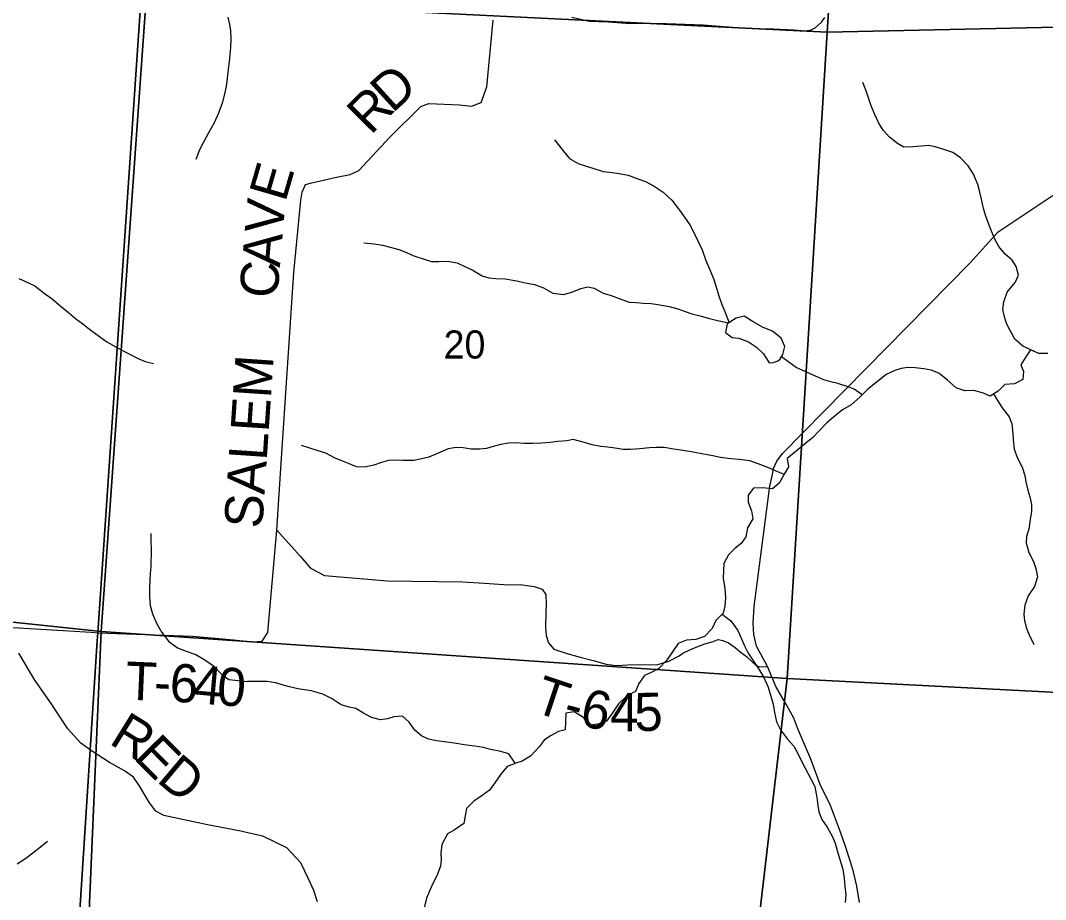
# Model space of a CAD drawing. Extents: x 1578669 to 1989827, y 208020 to 553079.
# Drawn here: x 1860103 to 1868162, y 355126 to 362037 of the extents above; entities that cross this region are included whole.
import ezdxf

# ---------------------------------------------------------------- set-up
doc = ezdxf.new("R2010")
doc.units = 0
for name, color, linetype in [('GM_X_County_Road', 7, 'Continuous'), ('GM_X_County_Road_Text', 7, 'Continuous'), ('GM_X_Minor_Lake', 7, 'Continuous'), ('GM_X_Minor_River', 7, 'Continuous'), ('GM_X_Section', 7, 'Continuous'), ('GM_X_Section_Text', 7, 'Continuous'), ('GM_X_State_Route', 7, 'Continuous'), ('GM_X_Township', 7, 'Continuous'), ('GM_X_Township_Road', 7, 'Continuous'), ('GM_X_Township_Road_Text', 7, 'Continuous')]:
    doc.layers.add(name, color=color, linetype=linetype)

msp = doc.modelspace()

# ---------------------------------------------------------------- linework, layer by layer
at = {"layer": 'GM_X_County_Road'}
for points in [[(1860670, 356290.4), (1860650.8, 356302.9), (1860578.7, 356356.7), (1860476.4, 356467.9), (1860338.5, 356674.7), (1860216.3, 356850.3), (1860089.2, 357063.4)], [(1861902.3, 355649.3), (1861835.4, 355664.6), (1861572.8, 355714.5), (1861230.9, 355786.4), (1861166.3, 355820.1), (1861116.8, 355887.6), (1861036.7, 356023.2), (1860992.2, 356087.7), (1860921.1, 356138.8), (1860803.3, 356203.3), (1860670, 356290.4)], [(1862438.6, 355108.2), (1862410.6, 355196.7), (1862364.6, 355295.2), (1862308.5, 355415.9), (1862198.1, 355532.7), (1862008.5, 355625), (1861902.3, 355649.3)]]:
    msp.add_lwpolyline(points, dxfattribs=at)
at = {"layer": 'GM_X_Minor_Lake'}
for points in [[(1866097.8, 359412.4), (1866112.2, 359474.4), (1866084.6, 359540.7), (1866015, 359595.1), (1865943.2, 359623.6), (1865863.5, 359668.1), (1865791.9, 359712.6), (1865729.8, 359697), (1865659.5, 359651.3), (1865645.1, 359585.3), (1865698.9, 359545), (1865750.8, 359538.7), (1865826.6, 359512.2), (1865890.3, 359469.8), (1865943.9, 359415.4), (1865989.5, 359345)], [(1865989.5, 359345), (1866021.7, 359347.6), (1866053.1, 359359.4), (1866073.8, 359373.1), (1866097.8, 359412.4)]]:
    msp.add_lwpolyline(points, dxfattribs=at)
at = {"layer": 'GM_X_Minor_River'}
for points in [[(1861732.7, 362063.6), (1861747.6, 362005.2), (1861754.6, 361955), (1861757.4, 361892.8), (1861754.1, 361822.7), (1861749.1, 361770.7), (1861744, 361712.7), (1861736.8, 361654.7), (1861727.4, 361582.8), (1861720.2, 361518.8), (1861707.1, 361460.9), (1861691.8, 361395.1), (1861660.1, 361309.5), (1861626.6, 361234), (1861578.9, 361148.8), (1861541.6, 361081.4), (1861510.4, 361019.9), (1861480.9, 360944.3)], [(1868110.9, 359418.4), (1867985.3, 359477.2), (1867921.7, 359531.7), (1867886.1, 359594), (1867854.5, 359654.2), (1867838.8, 359708.4), (1867827.2, 359764.5), (1867833.6, 359824.5), (1867862, 359900.5), (1867924.5, 359976.2), (1867950.8, 360034.1), (1867931.2, 360102.3), (1867899.6, 360152.5), (1867843.9, 360200.9), (1867796.3, 360261.3), (1867762.7, 360317.5), (1867731.2, 360393.8), (1867711.5, 360448), (1867693.8, 360498.2), (1867674.2, 360560.4), (1867658.7, 360632.5), (1867645, 360688.7), (1867629.4, 360746.8), (1867595.9, 360829.1), (1867554.3, 360893.5), (1867492.8, 360957.9), (1867433.1, 360998.3), (1867355.3, 361026.8), (1867295.4, 361045.2), (1867243.5, 361053.5), (1867183.5, 361049.9), (1867121.5, 361044.2), (1867049.5, 361042.7), (1866997.7, 361071), (1866936.1, 361121.4), (1866886.4, 361175.8), (1866852.8, 361230.1), (1866817.3, 361302.3), (1866791.7, 361366.6), (1866772, 361420.8), (1866754.4, 361476.9), (1866726.8, 361549.2)], [(1864301.2, 361099.1), (1864370.6, 361012.6), (1864420.2, 360952.3), (1864488, 360913.8), (1864549.8, 360893.4), (1864603.7, 360875.1), (1864683.5, 360850.6), (1864755.4, 360842.1), (1864809.3, 360833.8), (1864881.2, 360821.4), (1864965, 360788.8), (1865016.8, 360770.5), (1865084.6, 360736), (1865156.2, 360687.6), (1865223.8, 360625.1), (1865283.3, 360546.6), (1865322.9, 360492.3), (1865364.5, 360430), (1865398.1, 360371.8), (1865429.7, 360305.5), (1865463.3, 360233.2), (1865492.7, 360150.9), (1865526.2, 360072.6), (1865555.8, 360000.4), (1865579.3, 359924.1), (1865594.9, 359872), (1865618.5, 359805.8), (1865640.2, 359749.6), (1865674, 359660.8)], [(1862802.9, 360289.2), (1862884.8, 360280.7), (1862948.7, 360270.3), (1863020.6, 360251.8), (1863078.4, 360237.5), (1863138.3, 360213.1), (1863196.1, 360186.7), (1863275.9, 360160.2), (1863333.7, 360143.8), (1863391.7, 360143.5), (1863459.7, 360145.1), (1863535.6, 360132.6), (1863601.3, 360100.2), (1863653.2, 360075.8), (1863732.8, 360029.3), (1863786.7, 360013), (1863840.6, 360008.6), (1863914.6, 360006.2), (1864004.4, 359989.6), (1864070.3, 359975.2), (1864144.2, 359960.8), (1864216, 359934.3), (1864289.7, 359893.8), (1864373.6, 359883.3), (1864437.7, 359900.9), (1864507.8, 359930.5), (1864561.9, 359944.2), (1864613.8, 359931.9), (1864683.5, 359893.5), (1864747.4, 359875.1), (1864811.2, 359852.6), (1864889, 359824.1), (1864944.9, 359819.8), (1864998.9, 359815.5), (1865060.8, 359811.1), (1865114.8, 359804.8), (1865204.6, 359788.2), (1865272.5, 359769.8), (1865328.3, 359749.4), (1865382.2, 359731.1), (1865448, 359714.7), (1865509.9, 359698.3), (1865583.7, 359679.8), (1865672.1, 359659.5)], [(1860089.5, 360009.8), (1860141.1, 359984.7), (1860216.5, 359951.2), (1860289.5, 359893.6), (1860352.7, 359850.3), (1860425.6, 359786.7), (1860480.7, 359741.5), (1860535.9, 359694.3), (1860593.2, 359653.1), (1860644.4, 359610), (1860695.7, 359574.9), (1860780.6, 359511.1), (1860853.9, 359471.6), (1860925.2, 359432.1), (1860976.8, 359407.1), (1861032.3, 359377.9), (1861083.9, 359356.8), (1861149.6, 359339.5)], [(1868110.9, 359418.4), (1868045.1, 359448.8), (1868008.8, 359393), (1867968.4, 359331.2), (1867988.1, 359279), (1867983.7, 359214.9), (1867919.5, 359181.3), (1867843.5, 359175.7), (1867791.2, 359124), (1867727, 359084.3), (1867675.2, 359106.6), (1867599.3, 359127.1), (1867527.4, 359125.6), (1867459.5, 359150), (1867391.9, 359208.5), (1867324.3, 359264.9), (1867264.5, 359289.3), (1867204.6, 359299.7), (1867136.7, 359306.1), (1867080.7, 359308.4), (1867026.7, 359300.8), (1866976.6, 359285), (1866910.4, 359253.4), (1866828.1, 359189.8), (1866765.8, 359140.1), (1866703.4, 359076.4), (1866633.1, 359016.8), (1866564.9, 358977.1), (1866496.5, 358917.5), (1866442.3, 358873.8), (1866384, 358812), (1866331.6, 358758.3), (1866277.4, 358714.5), (1866203, 358650.9), (1866130.7, 358593.3), (1866142.3, 358527.1), (1866108, 358471.3), (1866069.5, 358399.4), (1866015.3, 358355.7), (1865937.4, 358364.2), (1865867.4, 358360.6), (1865825.1, 358304.8), (1865824.7, 358250.7), (1865850.3, 358182.5), (1865859.9, 358118.3), (1865819.5, 358048.5), (1865807, 357978.5), (1865770.7, 357926.7), (1865718.5, 357886.9), (1865670.2, 357835.2), (1865633.8, 357769.3), (1865629.5, 357713.2), (1865627.1, 357653.2), (1865640.6, 357571), (1865646.1, 357500.9), (1865641.7, 357432.8), (1865627.4, 357376.9), (1865569.1, 357319.1), (1865540.7, 357257.2), (1865480.3, 357195.5), (1865414.2, 357171.9), (1865340.2, 357164.3), (1865274.1, 357138.7), (1865229.7, 357072.9), (1865181.3, 357005.1), (1865122.9, 356941.4), (1865062.8, 356911.7), (1865008.6, 356888), (1864964.3, 356824.2), (1864937.9, 356762.3), (1864871.7, 356726.6), (1864805.3, 356665), (1864758.9, 356593.1), (1864710.5, 356529.4), (1864642.4, 356505.7), (1864582.4, 356498.1), (1864528.8, 356558.5), (1864455.1, 356601), (1864391.1, 356591.3), (1864388.7, 356523.3), (1864384.3, 356461.2), (1864334.2, 356447.5), (1864270, 356413.9), (1864219.8, 356378.1), (1864181.5, 356326.3), (1864113.1, 356252.6), (1864046.9, 356213), (1863996.8, 356199.2), (1863928.7, 356171.6), (1863880.3, 356111.8), (1863831.9, 356044), (1863791.6, 355986.2), (1863733.4, 355944.5), (1863667.1, 355898.9), (1863610.8, 355841.1), (1863598.4, 355783.1), (1863588.1, 355723.1), (1863513.8, 355671.5), (1863459.6, 355643.8), (1863415.1, 355560), (1863408.7, 355491.9)], [(1866720.9, 359094.2), (1866657.9, 359138.8), (1866604, 359161.1), (1866530.2, 359183.6), (1866474.3, 359195.9), (1866418.4, 359212.3), (1866352.6, 359240.7), (1866278.9, 359275.2), (1866203.1, 359309.7), (1866086.7, 359394.2)], [(1868180.9, 359420), (1868110.9, 359418.4)], [(1867754.4, 359101.2), (1867784.8, 359049.9), (1867822.4, 358991.6), (1867877.9, 358921.2), (1867897.5, 358865), (1867905.1, 358790.9), (1867908.8, 358740.8), (1867916.3, 358666.7), (1867941.9, 358596.5), (1867979.4, 358526.2), (1868001, 358460), (1868006.7, 358409.9), (1868024.2, 358343.7), (1868037.9, 358291.5), (1868051.5, 358231.4), (1868053.2, 358177.3), (1868042.8, 358117.3), (1868030.3, 358039.3), (1868014, 357981.3), (1868009.7, 357931.3), (1868031.2, 357855.1), (1868068.7, 357782.8), (1868086.4, 357728.6), (1868100, 357662.4), (1868075.5, 357588.5), (1868027.1, 357514.7), (1868000.6, 357440.8), (1867992.2, 357370.7), (1867997.9, 357320.6), (1868009.5, 357264.5), (1868033.1, 357206.3), (1868070.7, 357132)], [(1866106.7, 358468.9), (1866040.1, 358495.7), (1865980.3, 358522.1), (1865902.6, 358550.6), (1865836.7, 358575), (1865754.9, 358585.5), (1865686.9, 358591.9), (1865607, 358602.4), (1865547.1, 358614.8), (1865473.2, 358627.3), (1865391.4, 358643.8), (1865329.5, 358654.1), (1865277.6, 358662.5), (1865221.6, 358670.8), (1865167.7, 358681.1), (1865099.8, 358681.5), (1865047.8, 358677.9), (1864973.8, 358670.3), (1864899.8, 358664.7), (1864841.8, 358665.1), (1864779.9, 358675.5), (1864720, 358683.8), (1864666, 358688.1), (1864598.1, 358700.6), (1864528.3, 358721), (1864448.5, 358743.5), (1864398.4, 358733.8), (1864328.4, 358726.2), (1864266.4, 358718.6), (1864198.4, 358713), (1864128.4, 358711.4), (1864062.5, 358711.8), (1863992.5, 358716.2), (1863940.5, 358714.5), (1863878.5, 358702.9), (1863818.4, 358687.2), (1863768.3, 358671.5), (1863714.4, 358667.8), (1863646.4, 358668.2), (1863584.5, 358678.6), (1863528.5, 358680.9), (1863466.5, 358669.3), (1863382.3, 358631.8), (1863314.1, 358604.1), (1863246.1, 358588.5), (1863196, 358576.8), (1863110.1, 358577.3), (1863050.1, 358581.7), (1862996.1, 358578), (1862942.1, 358562.3), (1862882, 358542.6), (1862807.9, 358525.1), (1862746, 358529.4), (1862682.1, 358553.8), (1862630.3, 358574.2), (1862572.5, 358598.5), (1862502.7, 358635), (1862442.9, 358653.4), (1862379, 358673.8), (1862311.2, 358696.2)], [(1861127.9, 358005.2), (1861128.9, 357951.1), (1861129.4, 357872.9), (1861126.8, 357740.7), (1861123.8, 357690.6), (1861120.8, 357636.6), (1861117.6, 357574.5), (1861116.3, 357506.4), (1861123, 357438.1), (1861139.7, 357371.7), (1861176.3, 357294.8), (1861215, 357225.9), (1861267.7, 357158.7), (1861338.8, 357105.2), (1861406.4, 357079.8), (1861481.9, 357052.3), (1861553.2, 357010.8), (1861620.3, 356963.4), (1861685.1, 356895.9), (1861742.4, 356856.7), (1861814.3, 356847.3), (1861888.2, 356839.8)], [(1865621.3, 357370.8), (1865689, 357318.4), (1865742.5, 357242), (1865772.1, 357175.8), (1865795.7, 357119.6), (1865825.3, 357063.3), (1865861, 357009), (1865908.5, 356938.7), (1865948.1, 356872.4), (1865981.6, 356796.1), (1865999.2, 356733.9), (1866020.7, 356661.7), (1866030.3, 356597.6), (1866047.9, 356523.4), (1866079.5, 356461.1), (1866135, 356386.7), (1866182.6, 356332.3), (1866214.2, 356274.1), (1866241.9, 356219.8), (1866271.5, 356159.6), (1866320.9, 356071.2), (1866348.6, 356015), (1866364, 355928.8), (1866371.6, 355866.7), (1866379.3, 355816.6), (1866402.9, 355754.3), (1866446.5, 355694), (1866486, 355623.7), (1866507.7, 355569.5), (1866525.3, 355511.3), (1866544.9, 355441.1), (1866568.4, 355364.9), (1866579.9, 355292.8), (1866585.6, 355232.6), (1866591.1, 355162.5), (1866586.7, 355102.5)], [(1863993, 356197.7), (1863943.3, 356271.6), (1863879.5, 356290), (1863799.6, 356306.5), (1863743.7, 356320.9), (1863675.8, 356331.3), (1863591.9, 356343.8), (1863532, 356352.2), (1863456.1, 356364.7), (1863374.2, 356375.2), (1863310.3, 356387.6), (1863256.5, 356413.9), (1863204.8, 356458.3), (1863159.2, 356520.6), (1863105.6, 356567), (1863039.6, 356561.4), (1862987.5, 356545.7), (1862933.5, 356540), (1862861.6, 356556.4), (1862799.9, 356590.8), (1862740.1, 356627.2), (1862686.2, 356639.6), (1862624.4, 356658), (1862552.7, 356704.5), (1862480.9, 356740.9), (1862387.2, 356767.5), (1862335.2, 356775.8), (1862283.3, 356782.2), (1862219.4, 356798.6), (1862167.5, 356812.9), (1862111.7, 356829.2), (1862043.8, 356841.7), (1861888.2, 356839.8)], [(1860076.8, 355406.5), (1860143.8, 355451.3), (1860210.8, 355500.1), (1860261.6, 355541.2), (1860316.5, 355584.2)], [(1863408.7, 355491.9), (1863410.4, 355441.9), (1863404.1, 355387.8), (1863375.6, 355311.9), (1863347.3, 355258), (1863325, 355206.1), (1863294.6, 355138.2), (1863278.1, 355060.2)]]:
    msp.add_lwpolyline(points, dxfattribs=at)
at = {"layer": 'GM_X_Section'}
for points in [[(1861472.6, 367986), (1866798.8, 367601.9), (1866446.1, 361945.5), (1861091.5, 362209.9)], [(1866798.8, 367601.9), (1872183.4, 367145.3), (1871754, 361853.5), (1869336.4, 362007.7), (1866446.1, 361945.5)], [(1856112.7, 362911.8), (1861091.5, 362209.9), (1860737.7, 357233.4), (1855700.1, 357765.6)], [(1861091.5, 362209.9), (1866446.1, 361945.5), (1866130.8, 356864.4), (1860737.7, 357233.4)], [(1866446.1, 361945.5), (1869336.4, 362007.7), (1871754, 361853.5), (1871398.1, 356592.4), (1866130.8, 356864.4)], [(1855700.1, 357765.6), (1860737.7, 357233.4), (1860524.1, 352292.2), (1855214.2, 352367.7)], [(1860737.7, 357233.4), (1866130.8, 356864.4), (1865572.4, 352090.1), (1860524.1, 352292.2)], [(1866130.8, 356864.4), (1871398.1, 356592.4), (1871076.6, 351475.2), (1867993.2, 351687.8), (1865572.4, 352090.1)]]:
    msp.add_lwpolyline(points, close=True, dxfattribs=at)
at = {"layer": 'GM_X_State_Route'}
msp.add_lwpolyline([(1866700.4, 355104), (1866679.2, 355230.7), (1866651.8, 355343.3), (1866628.3, 355423.7), (1866589, 355542.4), (1866549.5, 355655.2), (1866472.7, 355866.5), (1866391.5, 356031.7), (1866316.5, 356230.9), (1866213.8, 356468.6), (1866184.2, 356551.1), (1866124.7, 356657.9), (1866043.3, 356795), (1865976.1, 356959.7), (1865888.9, 357119.4), (1865869.5, 357209.8), (1865864.1, 357300.2), (1865870.9, 357430.6), (1865995.7, 358377), (1866016.3, 358467.2), (1866022.7, 358515.3), (1866049.2, 358573.3), (1866093.7, 358633.2), (1867566.9, 360129.4), (1867791.4, 360374.6), (1868333.7, 360737.8)], dxfattribs=at)
at = {"layer": 'GM_X_Township'}
for points in [[(1859031.2, 376400.1), (1860929.1, 376280.6), (1862026.2, 376219.4), (1861697.2, 371438.7), (1861646.3, 370710.7), (1861408.8, 367950.9), (1861213, 364441.1), (1861197.1, 363836.4), (1861045.8, 362151.1), (1860710.3, 357224), (1860706, 357161.1), (1860650.8, 356302.9), (1860040.1, 346806.3)], [(1882646.6, 364366.3), (1882063.5, 357591.4), (1881944.6, 356212.8), (1881936, 356109.2), (1881810.5, 354649.5), (1881525.9, 351342.7), (1881414.8, 350049.3), (1881322.2, 347940.9), (1881165.8, 345493.3), (1878346.3, 345681.9), (1874430.1, 345924.2), (1871549.1, 346086.1), (1870033, 346179.3), (1867333.5, 346362.4), (1865771, 346465.4), (1860040.1, 346806.3), (1860650.8, 356302.9), (1860706, 357161.1), (1860710.3, 357224), (1861045.8, 362151.1)]]:
    msp.add_lwpolyline(points, dxfattribs=at)
at = {"layer": 'GM_X_Township_Road'}
for points in [[(1860657.8, 357227.2), (1860710.3, 357224), (1861457, 357197.2), (1861777.1, 357168.3), (1861928.4, 357152.8), (1862003.7, 357158), (1862048, 357226.2), (1862119.6, 358031.3), (1862152.6, 358557.4), (1862253.4, 360057.4), (1862306.5, 360623.6), (1862316.6, 360687.8), (1862344.8, 360748), (1862393.1, 360759.9), (1862588.1, 360805.5), (1862694.6, 360827.3), (1862763, 360857.2), (1863010.5, 361123.6), (1863250, 361361.9), (1863314.4, 361385.8), (1863555.5, 361375.1), (1863647.9, 361362.8), (1863724.3, 361392.6), (1863768.7, 361515), (1863819.8, 362039.1)], [(1864436.7, 362063.4), (1864575.3, 362032.8), (1864726, 362026.4), (1864896.8, 362013.8), (1865111.8, 362017.2), (1865471.5, 362004.1), (1865803, 361977.1), (1866024, 361972.4), (1866184.8, 361963.9), (1866277.2, 361955.6), (1866319.4, 361963.5), (1866351.5, 361979.5), (1866399.8, 362025.5), (1866426, 362061.6)], [(1862119.6, 358031.3), (1862304.1, 357823.9), (1862382.4, 357731.3), (1862492.8, 357674.7), (1862989.1, 357631.1), (1863579.9, 357623.4), (1863752.6, 357614.8), (1863939.5, 357600.2), (1864031.9, 357601.9), (1864142.4, 357587.6), (1864204.7, 357567.3), (1864232.8, 357525), (1864236.7, 357446.7), (1864232.6, 357384.5), (1864230.4, 357268), (1864236.3, 357201.7), (1864254.3, 357143.4), (1864296.4, 357095.1), (1864390.8, 357062.7), (1864503.3, 357032.2), (1864605.7, 357005.8), (1864708.1, 356977.4), (1864786.5, 356967.1), (1864878.9, 356970.9), (1864959.4, 356974.6), (1865051.8, 356972.4), (1865114.1, 356974.2), (1865200.5, 357000.1), (1865280.9, 357042), (1865311.1, 357062), (1865359.4, 357088), (1865415.7, 357109.9), (1865484.1, 357135.8), (1865548.4, 357155.7), (1865588.6, 357169.7), (1865624.7, 357161.5), (1865668.9, 357145.3), (1865721.1, 357109), (1865759.3, 357076.7), (1865811.4, 357036.5), (1865849.5, 357000.2), (1865887.7, 356965.9), (1865915.8, 356955.8), (1865976.1, 356959.7)], [(1859997.7, 357267.5), (1860657.8, 357227.2)]]:
    msp.add_lwpolyline(points, dxfattribs=at)

# ---------------------------------------------------------------- texts
at = {"layer": 'GM_X_County_Road_Text'}
for s, rotation, p in [('R', 328.27513, (1860790.8, 356356.7)), ('E', 314.50606, (1860985.5, 356239)), ('D', 319.8874, (1861165, 356058.4))]:
    msp.add_text(s, height=300, rotation=rotation, dxfattribs=at).set_placement(p)
at = {"layer": 'GM_X_Section_Text'}
msp.add_text('20', height=221, rotation=0.00001, dxfattribs=at).set_placement((1863429.8, 359379.6))
at = {"layer": 'GM_X_Township_Road_Text'}
for s, rotation, p in [('D', 42.30725, (1863026.3, 361302.9)), ('R', 45.34496, (1862856.1, 361130.5)), ('E', 73.74613, (1862184.6, 360602.8)), ('V', 85.02489, (1862164.5, 360355.1)), ('A', 85.18752, (1862142.4, 360092.3)), ('C', 85.17801, (1862121.7, 359846.7)), ('SALEM', 86.15743, (1862002.9, 358039.2)), ('T', 357.51771, (1860923.6, 356698.7)), ('6', 356.7405, (1861269.8, 356683.4)), ('4', 354.91913, (1861451.8, 356673)), ('0', 355.86108, (1861641.2, 356656.2)), ('T', 341.51491, (1864123.2, 356608)), ('-', 357.35278, (1861147.6, 356689)), ('6', 347.93156, (1864490.6, 356496.2)), ('4', 359.65878, (1864737.7, 356450.3)), ('5', 1.41922, (1864932.6, 356449.3)), ('-', 345.42934, (1864357.4, 356530.5))]:
    msp.add_text(s, height=300, rotation=rotation, dxfattribs=at).set_placement(p)

doc.saveas('drawing.dxf')
